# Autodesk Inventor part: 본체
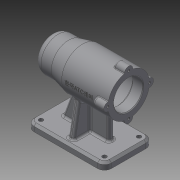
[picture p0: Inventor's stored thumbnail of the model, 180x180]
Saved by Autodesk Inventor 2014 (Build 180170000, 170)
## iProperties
Created: 2019-07
Part Number: 본체
Material: Generic
Document SubType Name: Modeling
Designer: kh
Density: 1 g/cm^3
Appearance: Default
Author: kh
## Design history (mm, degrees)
sketch "Sketch1"
  geometry: C1 r 30 at (0, 0); 1 further point
  constraints: 1 centre point, 1 coincident
  dimensions: "d0" = 60 diameter of C1
extrude "Extrusion1" new body sketch "Sketch1" distance "d1" = 67; taper "d2" = 0 deg
sketch "Sketch2"
  geometry: L1 (0, 0)-(-112, 0); L2 (-112, 25)-(-87, 25); L3 (0, 30)-(-67, 30) reference; L4 (-67, 30)-(-87, 25); L5 (-112, 25)-(-112, 0); L6 (-67, 30)-(-67, 0)
  constraints: 10 end point, 1 horizontal, 1 parallel, 1 perpendicular, 1 point on line
  dimensions: "d3" = 112 distance of L1.start L1.end; "d4" = 50 diameter of L2 L1; "d5" = 25 distance of L2.start L2.end; "d6" = 45 horizontal distance of L3.end L2.start
revolve "Revolution1" sketch "Sketch2" stored, may be unused: angle "d7" = 90 deg
workplane "Work Plane1"
sketch "Sketch4"
  geometry: L1 (112, 35)-(0, 35); L2 (0, 35)-(0, -35); L3 (0, -35)-(112, -35); L4 (112, -35)-(112, 35); L5 (112, 35)-(0, -35); L6 (0, 35)-(112, -35); 3 further points
  constraints: 12 end point, 3 midpoint, 2 parallel, 1 horizontal, 1 horizontal alignment, 1 perpendicular, 1 vertical alignment
  dimensions: "d10" = 112 distance of L1.start L1.end; "d11" = 70 distance of L1.end L2.end
extrude "Extrusion2" join sketch "Sketch4" distance "d12" = 10; taper "d13" = 0 deg
fillet "Fillet2" dims "d14" = 10
chamfer "Chamfer1" distance "d16" = 3; stored, may be unused: second distance "d17" = 2, angle "d18" = 45 deg
sketch "Sketch5"
  geometry: C1 r 6 at (0, 30); 2 further points
  constraints: 2 vertical alignment, 1 centre point, 1 other
  dimensions: "d55" = 12 diameter of C1
extrude "Extrusion3" join sketch "Sketch5" distance "d56" = 16; taper "d57" = 0 deg
hole "Hole5" diameter "d60" = 3.242; stored, may be unused: countersink angle "d64" = 90 deg, drill point angle "d66" = 118 deg; dims "d58" = 10, "d59" = 10, "d61" = 8, "d62" = 4, "d63" = 2, "d65" = 11
pattern_circular "Circular Pattern1" dims angle "d68" = 360 deg
fillet "Fillet4" dims "d70" = 3
fillet "Fillet5" dims "d71" = 1
sketch "Sketch8"
  geometry: L1 (-92, -70)-(-67.25, -2); L2 (-67.25, -2)-(-25, -2); L3 (-25, -2)-(-25, -70); L4 (-92, -70)-(-25, -70); L5 (-112, -80)-(-112, -73) reference; L6 (-109, -70)-(-102, -70) reference; L7 (0, -73)-(0, -80) reference; 1 further point
  constraints: 8 end point, 2 horizontal, 1 collinear, 1 perpendicular
  dimensions: "d99" = 110 deg angle of L1 L6; "d100" = 20 distance from line of L1.start L5; "d101" = 25 distance from line of L7 L3.end; "d102" = 68 distance between parallel lines of L4 L2
extrude "Extrusion4" join sketch "Sketch8" stored distance "d103" = 8; taper "d104" = 0 deg
sketch "Sketch6"
  geometry: L1 (0, 0)-(-112, 0); L2 (0, 0)-(0, 21); L3 (0, 21)-(-15, 21); L4 (-15, 21)-(-15, 24); L5 (-15, 24)-(-69, 24); L6 (-69, 24)-(-69, 21); L7 (-69, 21)-(-81, 21); L8 (-81, 21)-(-81, 17.5); L9 (-81, 17.5)-(-99, 17.5); L10 (-99, 17.5)-(-99, 16); L11 (-99, 16)-(-103, 16); L12 (-103, 16)-(-103, 10.5); L13 (-103, 10.5)-(-106, 10.5); L14 (-106, 10.5)-(-106, 0)
  constraints: 28 end point, 8 parallel, 3 perpendicular, 1 collinear, 1 horizontal, 1 point on line, 1 vertical
  dimensions: "d72" = 112 distance of L1.start L1.end; "d73" = 42 diameter of L3 L1; "d74" = 15 distance of L2.end L3.end; "d75" = 54 distance of L4.end L5.end; "d76" = 48 diameter of L5 L1; "d77" = 42 diameter of L7 L1; "d78" = 12 distance of L6.end L7.end; "d79" = 18 distance of L8.end L9.end; "d80" = 4 distance of L10.end L11.end; "d81" = 3 distance of L12.end L13.end; "d82" = 35 diameter of L9 L1; "d83" = 32 diameter of L11 L1; "d84" = 21 diameter of L13 L1
revolve "Revolution2" sketch "Sketch6" stored, may be unused: angle "d85" = 90 deg
fillet "Fillet6" dims "d86" = 3
fillet "Fillet7" dims "d87" = 0.3
workplane "Work Plane2"
sketch "Sketch10"
  geometry: L1 (-3, 10)-(5.346, 57.334); L2 (-7, 10)-(0, 10) reference; L3 (-10, 0)-(-10, 7) reference; A1 r 30 centre (25, 80) between (-4.226, 73.229) and (18.229, 50.774) reference; 1 further point
  constraints: 2 end point, 1 point on circle, 1 point on line
  dimensions: "d105" = 100 deg angle of L1 L2; "d106" = 7 distance from line of L1.start L3
feature "Rib1" sketch "Sketch10" dims "d107" = 1, "d108" = 8, "d109" = 0, "d110" = 0, "d111" = 1, "d112" = 1
mirror "Mirror1"
fillet "Fillet8" dims "d113" = 3
fillet "Fillet9" dims "d114" = 3
hole "Hole6" diameter "d120" = 6; stored, may be unused: countersink angle "d124" = 90 deg, drill point angle "d126" = 118 deg; dims "d118" = 10, "d119" = 10, "d121" = 8, "d122" = 4, "d123" = 2, "d125" = 11
pattern_linear "Rectangular Pattern1"
chamfer "Chamfer2" distance "d131" = 1; stored, may be unused: second distance "d132" = 2, angle "d133" = 45 deg
workplane "Work Plane3"
sketch "Sketch12"
  geometry: L1 (0, 5.998)-(0, -5.998) reference; 3 further points
  constraints: 1 horizontal alignment, 1 midpoint, 1 other
  dimensions: "d134" = 42 distance from line of point (-42, 0) L1
emboss "Emboss1" sketch "Sketch12" dims "d135" = 0.5, "d136" = 0
fillet "Fillet10" dims "d139" = 3
body "Solid1"
